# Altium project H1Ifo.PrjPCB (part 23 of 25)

## Sheet IfoSqz4A.SchDoc: D1800185
size C; Engineer: Daniel Sigg; DocumentNumber: 8; Revision: 4; SheetNumber: 8; SheetTotal: 10
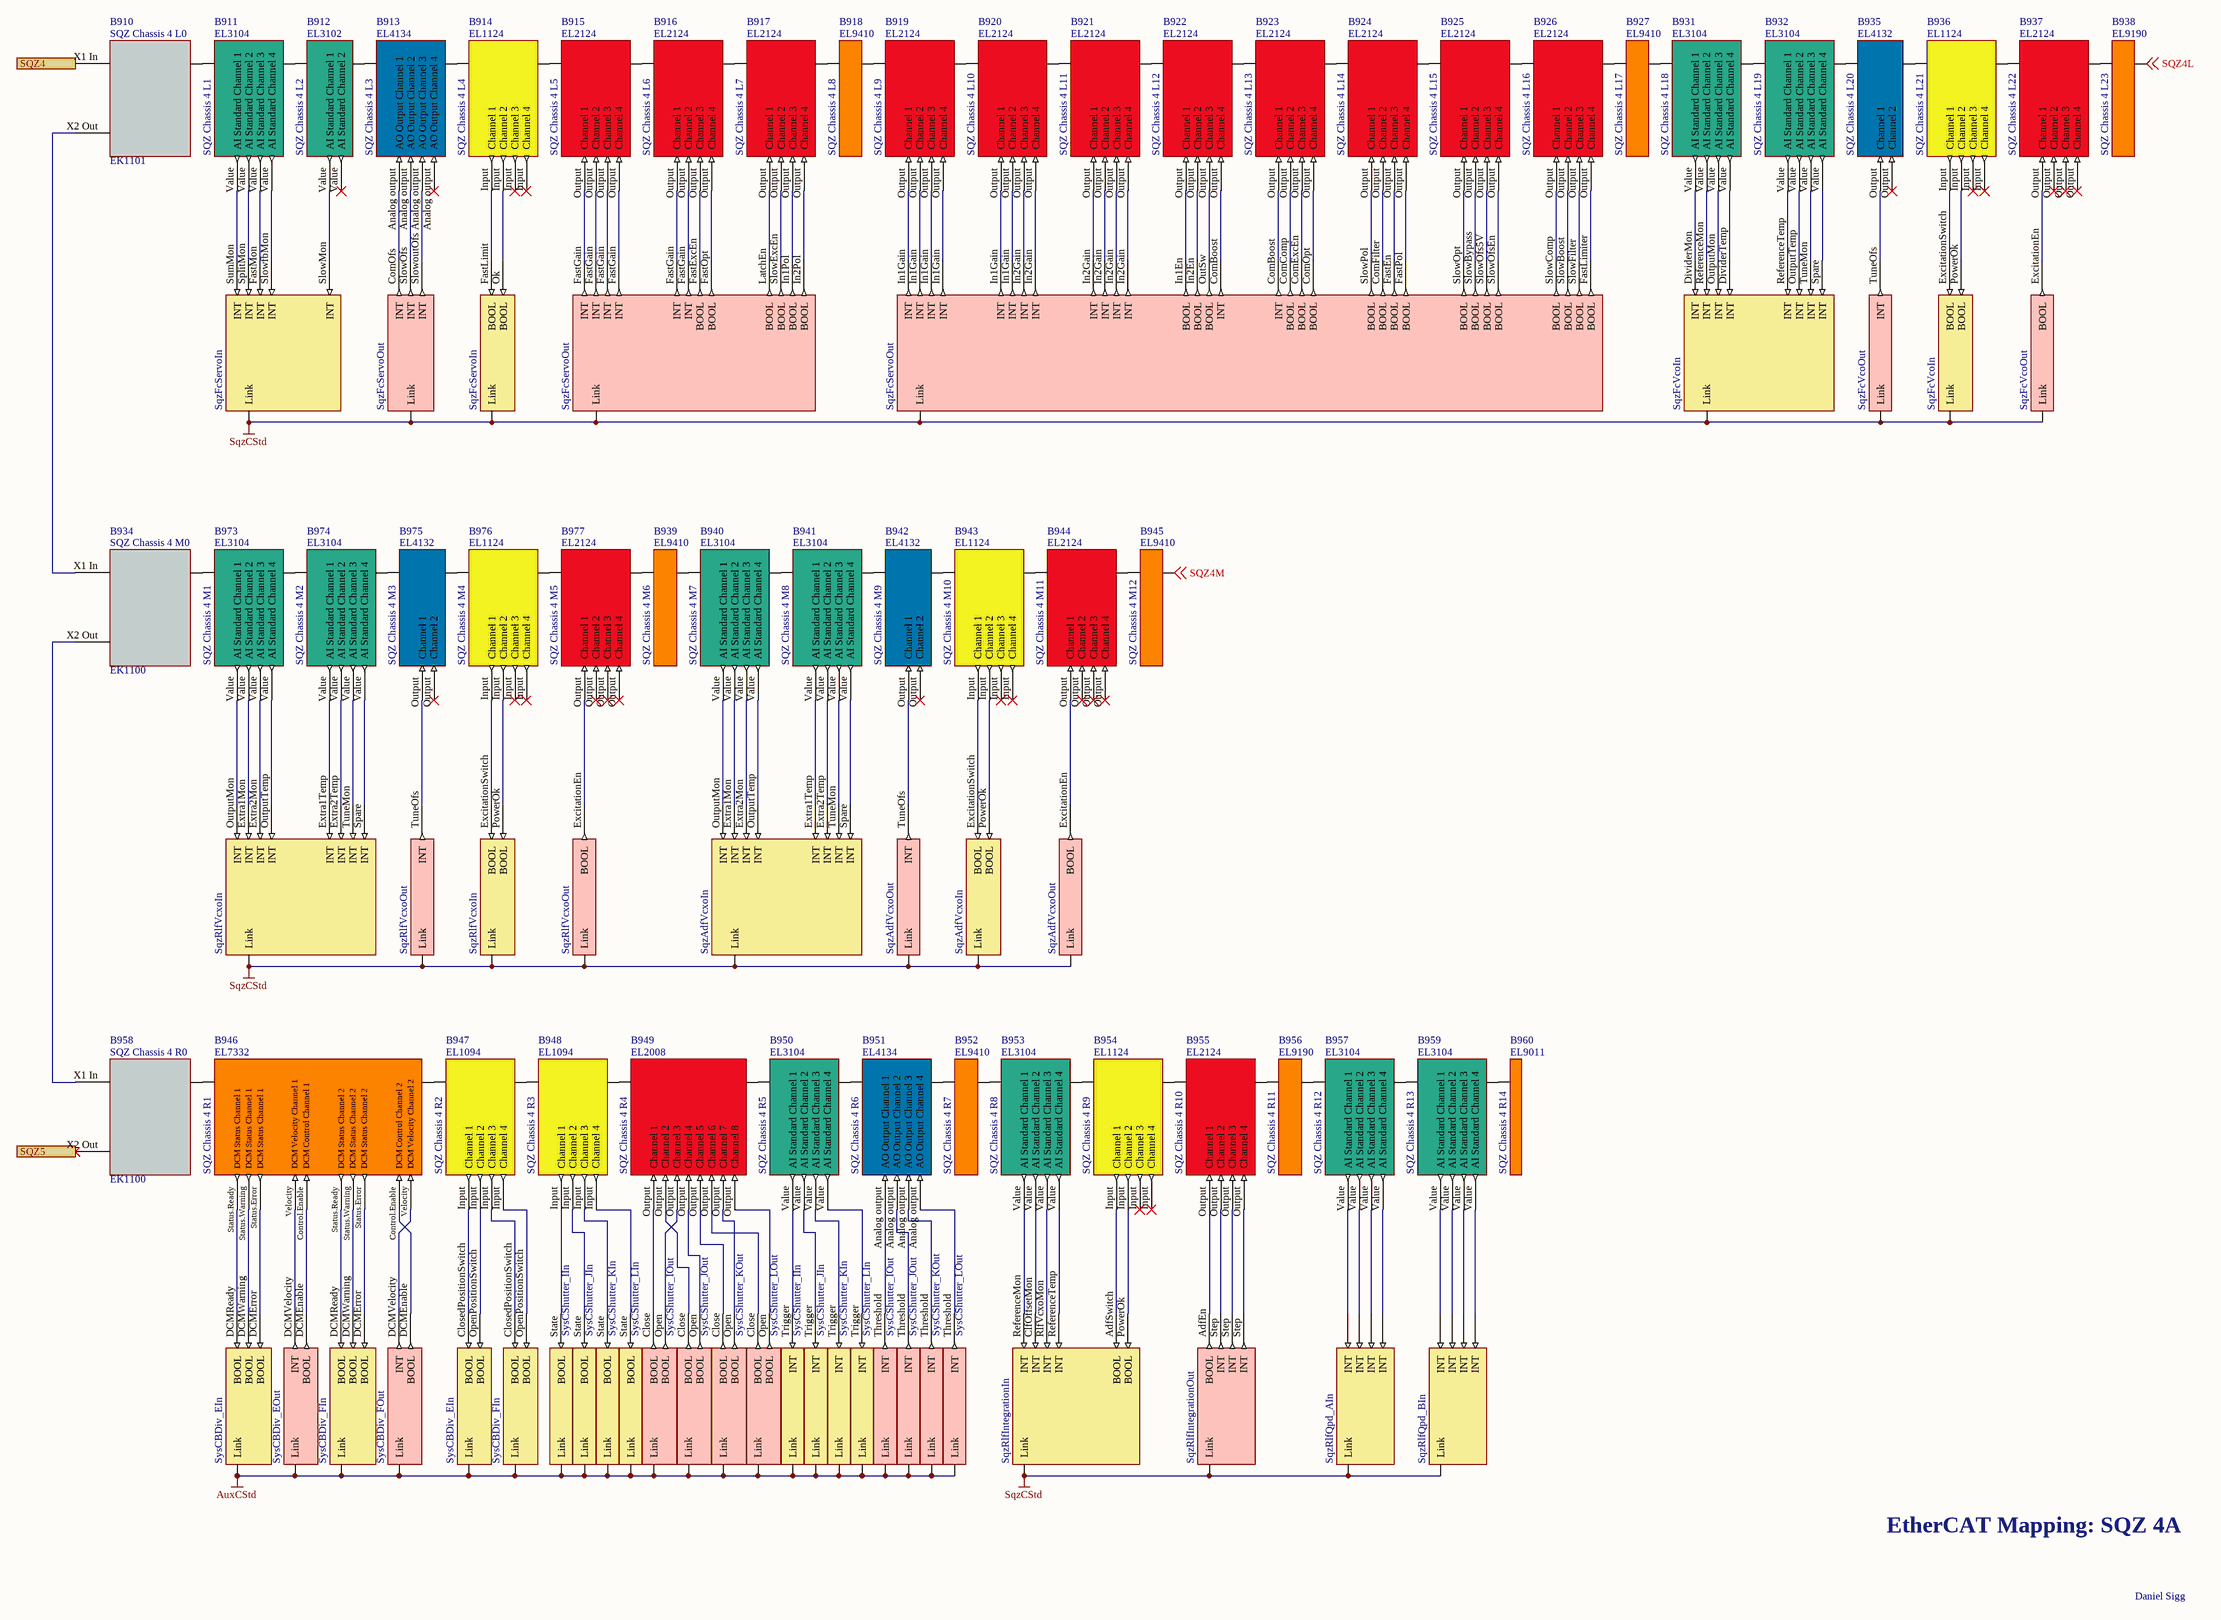
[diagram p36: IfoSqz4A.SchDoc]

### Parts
B910  SQZ Chassis 4 L0  Part Number: EK1101
B911  SQZ Chassis 4 L1  Part Number: EL3104  (mechanical)
B912  SQZ Chassis 4 L2  Part Number: EL3102  (mechanical)
B913  SQZ Chassis 4 L3  Part Number: EL4134  (mechanical)
B914  SQZ Chassis 4 L4  Part Number: EL1124  (mechanical)
B915  SQZ Chassis 4 L5  Part Number: EL2124  (mechanical)
B916  SQZ Chassis 4 L6  Part Number: EL2124  (mechanical)
B917  SQZ Chassis 4 L7  Part Number: EL2124  (mechanical)
B918  SQZ Chassis 4 L8  Part Number: EL9410  (mechanical)
B919  SQZ Chassis 4 L9  Part Number: EL2124  (mechanical)
B920  SQZ Chassis 4 L10  Part Number: EL2124  (mechanical)
B921  SQZ Chassis 4 L11  Part Number: EL2124  (mechanical)
B922  SQZ Chassis 4 L12  Part Number: EL2124  (mechanical)
B923  SQZ Chassis 4 L13  Part Number: EL2124  (mechanical)
B924  SQZ Chassis 4 L14  Part Number: EL2124  (mechanical)
B925  SQZ Chassis 4 L15  Part Number: EL2124  (mechanical)
B926  SQZ Chassis 4 L16  Part Number: EL2124  (mechanical)
B927  SQZ Chassis 4 L17  Part Number: EL9410  (mechanical)
B931  SQZ Chassis 4 L18  Part Number: EL3104  (mechanical)
B932  SQZ Chassis 4 L19  Part Number: EL3104  (mechanical)
B934  SQZ Chassis 4 M0  Part Number: EK1100
B935  SQZ Chassis 4 L20  Part Number: EL4132  (mechanical)
B936  SQZ Chassis 4 L21  Part Number: EL1124  (mechanical)
B937  SQZ Chassis 4 L22  Part Number: EL2124  (mechanical)
B938  SQZ Chassis 4 L23  Part Number: EL9190  (mechanical)
B939  SQZ Chassis 4 M6  Part Number: EL9410  (mechanical)
B940  SQZ Chassis 4 M7  Part Number: EL3104  (mechanical)
B941  SQZ Chassis 4 M8  Part Number: EL3104  (mechanical)
B942  SQZ Chassis 4 M9  Part Number: EL4132  (mechanical)
B943  SQZ Chassis 4 M10  Part Number: EL1124  (mechanical)
B944  SQZ Chassis 4 M11  Part Number: EL2124  (mechanical)
B945  SQZ Chassis 4 M12  Part Number: EL9410  (mechanical)
B946  SQZ Chassis 4 R1  Part Number: EL7332  (mechanical)
B947  SQZ Chassis 4 R2  Part Number: EL1094  (mechanical)
B948  SQZ Chassis 4 R3  Part Number: EL1094  (mechanical)
B949  SQZ Chassis 4 R4  Part Number: EL2008  (mechanical)
B950  SQZ Chassis 4 R5  Part Number: EL3104  (mechanical)
B951  SQZ Chassis 4 R6  Part Number: EL4134  (mechanical)
B952  SQZ Chassis 4 R7  Part Number: EL9410  (mechanical)
B953  SQZ Chassis 4 R8  Part Number: EL3104  (mechanical)
B954  SQZ Chassis 4 R9  Part Number: EL1124  (mechanical)
B955  SQZ Chassis 4 R10  Part Number: EL2124  (mechanical)
B956  SQZ Chassis 4 R11  Part Number: EL9190  (mechanical)
B957  SQZ Chassis 4 R12  Part Number: EL3104  (mechanical)
B958  SQZ Chassis 4 R0  Part Number: EK1100
B959  SQZ Chassis 4 R13  Part Number: EL3104  (mechanical)
B960  SQZ Chassis 4 R14  Part Number: EL9011  (mechanical)
B973  SQZ Chassis 4 M1  Part Number: EL3104  (mechanical)
B974  SQZ Chassis 4 M2  Part Number: EL3104  (mechanical)
B975  SQZ Chassis 4 M3  Part Number: EL4132  (mechanical)
B976  SQZ Chassis 4 M4  Part Number: EL1124  (mechanical)
B977  SQZ Chassis 4 M5  Part Number: EL2124  (mechanical)
V744  SqzFcServoIn  (parts A,B of 2)  (no BOM)
V745  SqzFcServoOut  (parts A,B,C of 3)  (no BOM)
V747  SqzFcVcoOut  (parts A,B of 2)  (no BOM)
V748  SysCBDiv_EOut  (no BOM)
V749  SysCBDiv_FOut  (no BOM)
V774  SqzRlfVcxoIn  (parts A,B of 2)  (no BOM)
V775  SqzRlfVcxoOut  (parts A,B of 2)  (no BOM)
V776  SqzAdfVcxoIn  (parts A,B of 2)  (no BOM)
V777  SqzAdfVcxoOut  (parts A,B of 2)  (no BOM)
V778  SysCBDiv_EIn  (parts A,B of 2)  (no BOM)
V779  SysCBDiv_FIn  (parts A,B of 2)  (no BOM)
V780  SysCShutter_IIn  (parts A,B of 2)  (no BOM)
V781  SysCShutter_JIn  (parts A,B of 2)  (no BOM)
V782  SysCShutter_KIn  (parts A,B of 2)  (no BOM)
V783  SysCShutter_LIn  (parts A,B of 2)  (no BOM)
V784  SysCShutter_IOut  (parts A,B of 2)  (no BOM)
V785  SysCShutter_JOut  (parts A,B of 2)  (no BOM)
V786  SysCShutter_KOut  (parts A,B of 2)  (no BOM)
V787  SysCShutter_LOut  (parts A,B of 2)  (no BOM)
V796  SqzFcVcoIn  (parts A,B of 2)  (no BOM)
V797  SqzRlfIntegrationIn  (no BOM)
V798  SqzRlfIntegrationOut  (no BOM)
V799  SqzRlfQpd_AIn  (no BOM)
V800  SqzRlfQpd_BIn  (no BOM)

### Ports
SQZ4, SQZ5

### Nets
AuxCStd: V748.0(Link) V749.0(Link) V778.0(Link) V778.1(Link) V779.0(Link) V779.1(Link) V780.0(Link) V780.1(Link) V781.0(Link) V781.1(Link) V782.0(Link) V782.1(Link) V783.0(Link) V783.1(Link) V784.0(Link) V784.1(Link) V785.0(Link) V785.1(Link) V786.0(Link) V786.1(Link) V787.0(Link) V787.1(Link)
SqzCStd: V744.0(Link) V744.1(Link) V745.0(Link) V745.1(Link) V745.2(Link) V747.0(Link) V747.1(Link) V774.0(Link) V774.1(Link) V775.0(Link) V775.1(Link) V776.0(Link) V776.1(Link) V777.0(Link) V777.1(Link) V796.0(Link) V796.1(Link) V797.0(Link) V798.1(Link) V799.1(Link) V800.1(Link)
SQZ4L: B938.Ebus(B) ; off-sheet SQZ4L
SQZ4M: B945.Ebus(B) ; off-sheet SQZ4M
NetB746#2_X1 In: B958.X2_Out(C) ; port SQZ5
NetB886_X2 Out: B910.X1_In(A) ; port SQZ4
NetB910_Ebus: B910.Ebus(B) B911.Ebus(A)
NetB910_X2 Out: B910.X2_Out(C) B934.X1_In(A)
NetB911_Ebus: B911.Ebus(B) B912.Ebus(A)
NetB911_Value: B911.Value(AI_Standard_Channel_1) V744.SumMon(INT)
NetB911_Value: B911.Value(AI_Standard_Channel_2) V744.SplitMon(INT)  [a separate net that carries the same name]
NetB911_Value: B911.Value(AI_Standard_Channel_3) V744.FastMon(INT)  [a separate net that carries the same name]
NetB911_Value: B911.Value(AI_Standard_Channel_4) V744.SlowfbMon(INT)  [a separate net that carries the same name]
NetB912_Ebus: B912.Ebus(B) B913.Ebus(A)
NetB912_Value: B912.Value(AI_Standard_Channel_1) V744.SlowMon(INT)
NetB913_Analog output: B913.Analog_output(AO_Output_Channel_1) V745.ComOfs(INT)
NetB913_Analog output: B913.Analog_output(AO_Output_Channel_2) V745.SlowOfs(INT)  [a separate net that carries the same name]
NetB913_Analog output: B913.Analog_output(AO_Output_Channel_3) V745.SlowoutOfs(INT)  [a separate net that carries the same name]
NetB913_Ebus: B913.Ebus(B) B914.Ebus(A)
NetB914_Ebus: B914.Ebus(B) B915.Ebus(A)
NetB914_Input: B914.Input(Channel_1) V744.FastLimit(BOOL)
NetB914_Input: B914.Input(Channel_2) V744.Ok(BOOL)  [a separate net that carries the same name]
NetB915_Ebus: B915.Ebus(B) B916.Ebus(A)
NetB915_Output: B915.Output(Channel_1) V745.FastGain(INT)
NetB915_Output: B915.Output(Channel_2) V745.FastGain(INT)  [a separate net that carries the same name]
NetB915_Output: B915.Output(Channel_3) V745.FastGain(INT)  [a separate net that carries the same name]
NetB915_Output: B915.Output(Channel_4) V745.FastGain(INT)  [a separate net that carries the same name]
NetB916_Ebus: B916.Ebus(B) B917.Ebus(A)
NetB916_Output: B916.Output(Channel_1) V745.FastGain(INT)
NetB916_Output: B916.Output(Channel_2) V745.FastGain(INT)  [a separate net that carries the same name]
NetB916_Output: B916.Output(Channel_3) V745.FastExcEn(BOOL)  [a separate net that carries the same name]
NetB916_Output: B916.Output(Channel_4) V745.FastOpt(BOOL)  [a separate net that carries the same name]
NetB917_Ebus: B917.Ebus(B) B918.Ebus(A)
NetB917_Output: B917.Output(Channel_1) V745.LatchEn(BOOL)
NetB917_Output: B917.Output(Channel_2) V745.SlowExcEn(BOOL)  [a separate net that carries the same name]
NetB917_Output: B917.Output(Channel_3) V745.In1Pol(BOOL)  [a separate net that carries the same name]
NetB917_Output: B917.Output(Channel_4) V745.In2Pol(BOOL)  [a separate net that carries the same name]
NetB918_Ebus: B918.Ebus(B) B919.Ebus(A)
NetB919_Ebus: B919.Ebus(B) B920.Ebus(A)
NetB919_Output: B919.Output(Channel_1) V745.In1Gain(INT)
NetB919_Output: B919.Output(Channel_2) V745.In1Gain(INT)  [a separate net that carries the same name]
NetB919_Output: B919.Output(Channel_3) V745.In1Gain(INT)  [a separate net that carries the same name]
NetB919_Output: B919.Output(Channel_4) V745.In1Gain(INT)  [a separate net that carries the same name]
NetB920_Ebus: B920.Ebus(B) B921.Ebus(A)
NetB920_Output: B920.Output(Channel_1) V745.In1Gain(INT)
NetB920_Output: B920.Output(Channel_2) V745.In1Gain(INT)  [a separate net that carries the same name]
NetB920_Output: B920.Output(Channel_3) V745.In2Gain(INT)  [a separate net that carries the same name]
NetB920_Output: B920.Output(Channel_4) V745.In2Gain(INT)  [a separate net that carries the same name]
NetB921_Ebus: B921.Ebus(B) B922.Ebus(A)
NetB921_Output: B921.Output(Channel_1) V745.In2Gain(INT)
NetB921_Output: B921.Output(Channel_2) V745.In2Gain(INT)  [a separate net that carries the same name]
NetB921_Output: B921.Output(Channel_3) V745.In2Gain(INT)  [a separate net that carries the same name]
NetB921_Output: B921.Output(Channel_4) V745.In2Gain(INT)  [a separate net that carries the same name]
NetB922_Ebus: B922.Ebus(B) B923.Ebus(A)
NetB922_Output: B922.Output(Channel_1) V745.In1En(BOOL)
NetB922_Output: B922.Output(Channel_2) V745.In2En(BOOL)  [a separate net that carries the same name]
NetB922_Output: B922.Output(Channel_3) V745.OutSw(BOOL)  [a separate net that carries the same name]
NetB922_Output: B922.Output(Channel_4) V745.ComBoost(INT)  [a separate net that carries the same name]
NetB923_Ebus: B923.Ebus(B) B924.Ebus(A)
NetB923_Output: B923.Output(Channel_1) V745.ComBoost(INT)
NetB923_Output: B923.Output(Channel_2) V745.ComComp(BOOL)  [a separate net that carries the same name]
NetB923_Output: B923.Output(Channel_3) V745.ComExcEn(BOOL)  [a separate net that carries the same name]
NetB923_Output: B923.Output(Channel_4) V745.ComOpt(BOOL)  [a separate net that carries the same name]
NetB924_Ebus: B924.Ebus(B) B925.Ebus(A)
NetB924_Output: B924.Output(Channel_1) V745.SlowPol(BOOL)
NetB924_Output: B924.Output(Channel_2) V745.ComFilter(BOOL)  [a separate net that carries the same name]
NetB924_Output: B924.Output(Channel_3) V745.FastEn(BOOL)  [a separate net that carries the same name]
NetB924_Output: B924.Output(Channel_4) V745.FastPol(BOOL)  [a separate net that carries the same name]
NetB925_Ebus: B925.Ebus(B) B926.Ebus(A)
NetB925_Output: B925.Output(Channel_1) V745.SlowOpt(BOOL)
NetB925_Output: B925.Output(Channel_2) V745.SlowBypass(BOOL)  [a separate net that carries the same name]
NetB925_Output: B925.Output(Channel_3) V745.SlowOfs5V(BOOL)  [a separate net that carries the same name]
NetB925_Output: B925.Output(Channel_4) V745.SlowOfsEn(BOOL)  [a separate net that carries the same name]
NetB926_Ebus: B926.Ebus(B) B927.Ebus(A)
NetB926_Output: B926.Output(Channel_1) V745.SlowComp(BOOL)
NetB926_Output: B926.Output(Channel_2) V745.SlowBoost(BOOL)  [a separate net that carries the same name]
NetB926_Output: B926.Output(Channel_3) V745.SlowFilter(BOOL)  [a separate net that carries the same name]
NetB926_Output: B926.Output(Channel_4) V745.FastLimiter(BOOL)  [a separate net that carries the same name]
NetB927_Ebus: B927.Ebus(B) B931.Ebus(A)
NetB931_Ebus: B931.Ebus(B) B932.Ebus(A)
NetB931_Value: B931.Value(AI_Standard_Channel_1) V796.DividerMon(INT)
NetB931_Value: B931.Value(AI_Standard_Channel_2) V796.ReferenceMon(INT)  [a separate net that carries the same name]
NetB931_Value: B931.Value(AI_Standard_Channel_3) V796.OutputMon(INT)  [a separate net that carries the same name]
NetB931_Value: B931.Value(AI_Standard_Channel_4) V796.DividerTemp(INT)  [a separate net that carries the same name]
NetB932_Ebus: B932.Ebus(B) B935.Ebus(A)
NetB932_Value: B932.Value(AI_Standard_Channel_1) V796.ReferenceTemp(INT)
NetB932_Value: B932.Value(AI_Standard_Channel_2) V796.OutputTemp(INT)  [a separate net that carries the same name]
NetB932_Value: B932.Value(AI_Standard_Channel_3) V796.TuneMon(INT)  [a separate net that carries the same name]
NetB932_Value: B932.Value(AI_Standard_Channel_4) V796.Spare(INT)  [a separate net that carries the same name]
NetB934_Ebus: B934.Ebus(B) B973.Ebus(A)
NetB934_X2 Out: B934.X2_Out(C) B958.X1_In(A)
NetB935_Ebus: B935.Ebus(B) B936.Ebus(A)
NetB935_Output: B935.Output(Channel_1) V747.TuneOfs(INT)
NetB936_Ebus: B936.Ebus(B) B937.Ebus(A)
NetB936_Input: B936.Input(Channel_1) V796.ExcitationSwitch(BOOL)
NetB936_Input: B936.Input(Channel_2) V796.PowerOk(BOOL)  [a separate net that carries the same name]
NetB937_Ebus: B937.Ebus(B) B938.Ebus(A)
NetB937_Output: B937.Output(Channel_1) V747.ExcitationEn(BOOL)
NetB939_Ebus: B939.Ebus(A) B977.Ebus(B)
NetB939_Ebus: B939.Ebus(B) B940.Ebus(A)  [a separate net that carries the same name]
NetB940_Ebus: B940.Ebus(B) B941.Ebus(A)
NetB940_Value: B940.Value(AI_Standard_Channel_1) V776.OutputMon(INT)
NetB940_Value: B940.Value(AI_Standard_Channel_2) V776.Extra1Mon(INT)  [a separate net that carries the same name]
NetB940_Value: B940.Value(AI_Standard_Channel_3) V776.Extra2Mon(INT)  [a separate net that carries the same name]
NetB940_Value: B940.Value(AI_Standard_Channel_4) V776.OutputTemp(INT)  [a separate net that carries the same name]
NetB941_Ebus: B941.Ebus(B) B942.Ebus(A)
NetB941_Value: B941.Value(AI_Standard_Channel_1) V776.Extra1Temp(INT)
NetB941_Value: B941.Value(AI_Standard_Channel_2) V776.Extra2Temp(INT)  [a separate net that carries the same name]
NetB941_Value: B941.Value(AI_Standard_Channel_3) V776.TuneMon(INT)  [a separate net that carries the same name]
NetB941_Value: B941.Value(AI_Standard_Channel_4) V776.Spare(INT)  [a separate net that carries the same name]
NetB942_Ebus: B942.Ebus(B) B943.Ebus(A)
NetB942_Output: B942.Output(Channel_1) V777.TuneOfs(INT)
NetB943_Ebus: B943.Ebus(B) B944.Ebus(A)
NetB943_Input: B943.Input(Channel_1) V776.ExcitationSwitch(BOOL)
NetB943_Input: B943.Input(Channel_2) V776.PowerOk(BOOL)  [a separate net that carries the same name]
NetB944_Ebus: B944.Ebus(B) B945.Ebus(A)
NetB944_Output: B944.Output(Channel_1) V777.ExcitationEn(BOOL)
NetB946_Control.Enable: B946.Control.Enable(DCM_Control_Channel_1) V748.DCMEnable(BOOL)
NetB946_Control.Enable: B946.Control.Enable(DCM_Control_Channel_2) V749.DCMEnable(BOOL)  [a separate net that carries the same name]
NetB946_Ebus: B946.Ebus(A) B958.Ebus(B)
NetB946_Ebus: B946.Ebus(B) B947.Ebus(A)  [a separate net that carries the same name]
NetB946_Status.Error: B946.Status.Error(DCM_Status_Channel_1) V778.DCMError(BOOL)
NetB946_Status.Error: B946.Status.Error(DCM_Status_Channel_2) V779.DCMError(BOOL)  [a separate net that carries the same name]
NetB946_Status.Ready: B946.Status.Ready(DCM_Status_Channel_1) V778.DCMReady(BOOL)
NetB946_Status.Ready: B946.Status.Ready(DCM_Status_Channel_2) V779.DCMReady(BOOL)  [a separate net that carries the same name]
NetB946_Status.Warning: B946.Status.Warning(DCM_Status_Channel_1) V778.DCMWarning(BOOL)
NetB946_Status.Warning: B946.Status.Warning(DCM_Status_Channel_2) V779.DCMWarning(BOOL)  [a separate net that carries the same name]
NetB946_Velocity: B946.Velocity(DCM_Velocity_Channel_1) V748.DCMVelocity(INT)
NetB946_Velocity: B946.Velocity(DCM_Velocity_Channel_2) V749.DCMVelocity(INT)  [a separate net that carries the same name]
NetB947_Ebus: B947.Ebus(B) B948.Ebus(A)
NetB947_Input: B947.Input(Channel_1) V778.ClosedPositionSwitch(BOOL)
NetB947_Input: B947.Input(Channel_2) V778.OpenPositionSwitch(BOOL)  [a separate net that carries the same name]
NetB947_Input: B947.Input(Channel_3) V779.ClosedPositionSwitch(BOOL)  [a separate net that carries the same name]
NetB947_Input: B947.Input(Channel_4) V779.OpenPositionSwitch(BOOL)  [a separate net that carries the same name]
NetB948_Ebus: B948.Ebus(B) B949.Ebus(A)
NetB948_Input: B948.Input(Channel_1) V780.State(BOOL)
NetB948_Input: B948.Input(Channel_2) V781.State(BOOL)  [a separate net that carries the same name]
NetB948_Input: B948.Input(Channel_3) V782.State(BOOL)  [a separate net that carries the same name]
NetB948_Input: B948.Input(Channel_4) V783.State(BOOL)  [a separate net that carries the same name]
NetB949_Ebus: B949.Ebus(B) B950.Ebus(A)
NetB949_Output: B949.Output(Channel_1) V784.Close(BOOL)
NetB949_Output: B949.Output(Channel_2) V785.Close(BOOL)  [a separate net that carries the same name]
NetB949_Output: B949.Output(Channel_3) V784.Open(BOOL)  [a separate net that carries the same name]
NetB949_Output: B949.Output(Channel_4) V785.Open(BOOL)  [a separate net that carries the same name]
NetB949_Output: B949.Output(Channel_5) V786.Close(BOOL)  [a separate net that carries the same name]
NetB949_Output: B949.Output(Channel_6) V787.Close(BOOL)  [a separate net that carries the same name]
NetB949_Output: B949.Output(Channel_7) V786.Open(BOOL)  [a separate net that carries the same name]
NetB949_Output: B949.Output(Channel_8) V787.Open(BOOL)  [a separate net that carries the same name]
NetB950_Ebus: B950.Ebus(B) B951.Ebus(A)
NetB950_Value: B950.Value(AI_Standard_Channel_1) V780.Trigger(INT)
NetB950_Value: B950.Value(AI_Standard_Channel_2) V781.Trigger(INT)  [a separate net that carries the same name]
NetB950_Value: B950.Value(AI_Standard_Channel_3) V782.Trigger(INT)  [a separate net that carries the same name]
NetB950_Value: B950.Value(AI_Standard_Channel_4) V783.Trigger(INT)  [a separate net that carries the same name]
NetB951_Analog output: B951.Analog_output(AO_Output_Channel_1) V784.Threshold(INT)
NetB951_Analog output: B951.Analog_output(AO_Output_Channel_2) V785.Threshold(INT)  [a separate net that carries the same name]
NetB951_Analog output: B951.Analog_output(AO_Output_Channel_3) V786.Threshold(INT)  [a separate net that carries the same name]
NetB951_Analog output: B951.Analog_output(AO_Output_Channel_4) V787.Threshold(INT)  [a separate net that carries the same name]
NetB951_Ebus: B951.Ebus(B) B952.Ebus(A)
NetB952_Ebus: B952.Ebus(B) B953.Ebus(A)
NetB953_Ebus: B953.Ebus(B) B954.Ebus(A)
NetB953_Value: B953.Value(AI_Standard_Channel_1) V797.ReferenceMon(INT)
NetB953_Value: B953.Value(AI_Standard_Channel_2) V797.ClfOffsetMon(INT)  [a separate net that carries the same name]
NetB953_Value: B953.Value(AI_Standard_Channel_3) V797.RlfVcxoMon(INT)  [a separate net that carries the same name]
NetB953_Value: B953.Value(AI_Standard_Channel_4) V797.ReferenceTemp(INT)  [a separate net that carries the same name]
NetB954_Ebus: B954.Ebus(B) B955.Ebus(A)
NetB954_Input: B954.Input(Channel_1) V797.AdfSwitch(BOOL)
NetB954_Input: B954.Input(Channel_2) V797.PowerOk(BOOL)  [a separate net that carries the same name]
NetB955_Ebus: B955.Ebus(B) B956.Ebus(A)
NetB955_Output: B955.Output(Channel_1) V798.AdfEn(BOOL)
NetB955_Output: B955.Output(Channel_2) V798.Step(INT)  [a separate net that carries the same name]
NetB955_Output: B955.Output(Channel_3) V798.Step(INT)  [a separate net that carries the same name]
NetB955_Output: B955.Output(Channel_4) V798.Step(INT)  [a separate net that carries the same name]
NetB956_Ebus: B956.Ebus(B) B957.Ebus(A)
NetB957_Ebus: B957.Ebus(B) B959.Ebus(A)
NetB957_Value: B957.Value(AI_Standard_Channel_1) V799.Seg4Dc(INT)
NetB957_Value: B957.Value(AI_Standard_Channel_2) V799.Seg3Dc(INT)  [a separate net that carries the same name]
NetB957_Value: B957.Value(AI_Standard_Channel_3) V799.Seg1Dc(INT)  [a separate net that carries the same name]
NetB957_Value: B957.Value(AI_Standard_Channel_4) V799.Seg2Dc(INT)  [a separate net that carries the same name]
NetB959_Ebus: B959.Ebus(B) B960.Ebus(A)
NetB959_Value: B959.Value(AI_Standard_Channel_1) V800.Seg4Dc(INT)
NetB959_Value: B959.Value(AI_Standard_Channel_2) V800.Seg3Dc(INT)  [a separate net that carries the same name]
NetB959_Value: B959.Value(AI_Standard_Channel_3) V800.Seg1Dc(INT)  [a separate net that carries the same name]
NetB959_Value: B959.Value(AI_Standard_Channel_4) V800.Seg2Dc(INT)  [a separate net that carries the same name]
NetB973_Ebus: B973.Ebus(B) B974.Ebus(A)
NetB973_Value: B973.Value(AI_Standard_Channel_1) V774.OutputMon(INT)
NetB973_Value: B973.Value(AI_Standard_Channel_2) V774.Extra1Mon(INT)  [a separate net that carries the same name]
NetB973_Value: B973.Value(AI_Standard_Channel_3) V774.Extra2Mon(INT)  [a separate net that carries the same name]
NetB973_Value: B973.Value(AI_Standard_Channel_4) V774.OutputTemp(INT)  [a separate net that carries the same name]
NetB974_Ebus: B974.Ebus(B) B975.Ebus(A)
NetB974_Value: B974.Value(AI_Standard_Channel_1) V774.Extra1Temp(INT)
NetB974_Value: B974.Value(AI_Standard_Channel_2) V774.Extra2Temp(INT)  [a separate net that carries the same name]
NetB974_Value: B974.Value(AI_Standard_Channel_3) V774.TuneMon(INT)  [a separate net that carries the same name]
NetB974_Value: B974.Value(AI_Standard_Channel_4) V774.Spare(INT)  [a separate net that carries the same name]
NetB975_Ebus: B975.Ebus(B) B976.Ebus(A)
NetB975_Output: B975.Output(Channel_1) V775.TuneOfs(INT)
NetB976_Ebus: B976.Ebus(B) B977.Ebus(A)
NetB976_Input: B976.Input(Channel_1) V774.ExcitationSwitch(BOOL)
NetB976_Input: B976.Input(Channel_2) V774.PowerOk(BOOL)  [a separate net that carries the same name]
NetB977_Output: B977.Output(Channel_1) V775.ExcitationEn(BOOL)

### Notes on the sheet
- EtherCAT Mapping: SQZ 4A
- Daniel Sigg

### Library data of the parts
B910 = CouplerEK1101: EtherCAT Coupler; Rail: Left; BoxNextB: JTLFXJNX; BoxNextC: CKSSHHCU; BoxPrev: BKUDMEPV; PortPrevFull: 1168/C; PortPrevShort: C 'X2 Out'; Fullname: TIID^Vertex Squeezer (EtherCAT)^SQZ Chassis 4 L0 (EK1101); BoxPorts: Junction; BoxAddr: 1188; Disabled: False
B911 = TerminalEL3104: EtherCAT Terminal EL3104 4-chn Analog Input; Rail: Left; BoxNextB: RXMGGCEI; BoxPrev: BCNOLNHC; PortPrevFull: 1188/B; PortPrevShort: B; Fullname: TIID^Vertex Squeezer (EtherCAT)^SQZ Chassis 4 L0 (EK1101)^SQZ Chassis 4 L1 (EL3104); BoxAddr: 1189; Disabled: False
B912 = TerminalEL3102: EtherCAT Terminal EL3102 2-chn Analog Input; Rail: Left; BoxNextB: QRUXMSAU; BoxPrev: JTLFXJNX; PortPrevFull: 1189/B; PortPrevShort: B; Fullname: TIID^Vertex Squeezer (EtherCAT)^SQZ Chassis 4 L0 (EK1101)^SQZ Chassis 4 L2 (EL3102); BoxAddr: 1190; Disabled: False
B913 = TerminalEL4134: EtherCAT Terminal EL4134 4-chn Analog Ouput; Rail: Left; BoxNextB: KEVJOHYG; BoxPrev: RXMGGCEI; PortPrevFull: 1190/B; PortPrevShort: B; Fullname: TIID^Vertex Squeezer (EtherCAT)^SQZ Chassis 4 L0 (EK1101)^SQZ Chassis 4 L3 (EL4134); BoxAddr: 1191; Disabled: False
B914 = TerminalEL1124: EtherCAT Terminal EL1124 4-chn Digital Input; Rail: Left; BoxNextB: XQQAHJLW; BoxPrev: QRUXMSAU; PortPrevFull: 1191/B; PortPrevShort: B; Fullname: TIID^Vertex Squeezer (EtherCAT)^SQZ Chassis 4 L0 (EK1101)^SQZ Chassis 4 L4 (EL1124); BoxAddr: 1192; Disabled: False
B915 = TerminalEL2124: EtherCAT Terminal EL2124 4-chn Digital Ouput; Rail: Left; BoxNextB: SEPSBOXG; BoxPrev: KEVJOHYG; PortPrevFull: 1192/B; PortPrevShort: B; Fullname: TIID^Vertex Squeezer (EtherCAT)^SQZ Chassis 4 L0 (EK1101)^SQZ Chassis 4 L5 (EL2124); BoxAddr: 1193; Disabled: False
B916 = TerminalEL2124: EtherCAT Terminal EL2124 4-chn Digital Ouput; Rail: Left; BoxNextB: EEVYYAYS; BoxPrev: XQQAHJLW; PortPrevFull: 1193/B; PortPrevShort: B; Fullname: TIID^Vertex Squeezer (EtherCAT)^SQZ Chassis 4 L0 (EK1101)^SQZ Chassis 4 L6 (EL2124); BoxAddr: 1194; Disabled: False
B917 = TerminalEL2124: EtherCAT Terminal EL2124 4-chn Digital Ouput; Rail: Left; BoxNextB: TYLYDKYN; BoxPrev: SEPSBOXG; PortPrevFull: 1194/B; PortPrevShort: B; Fullname: TIID^Vertex Squeezer (EtherCAT)^SQZ Chassis 4 L0 (EK1101)^SQZ Chassis 4 L7 (EL2124); BoxAddr: 1195; Disabled: False
B918 = TerminalEL9410: EtherCAT Terminal EL9410 Power; Rail: Left; BoxNextB: WFLVLTIK; BoxPrev: EEVYYAYS; PortPrevFull: 1195/B; PortPrevShort: B; Fullname: TIID^Vertex Squeezer (EtherCAT)^SQZ Chassis 4 L0 (EK1101)^SQZ Chassis 4 L8 (EL9410); BoxAddr: 1196; Disabled: False
B919 = TerminalEL2124: EtherCAT Terminal EL2124 4-chn Digital Ouput; Rail: Left; BoxNextB: FUNGBFOC; BoxPrev: TYLYDKYN; PortPrevFull: 1196/B; PortPrevShort: B; Fullname: TIID^Vertex Squeezer (EtherCAT)^SQZ Chassis 4 L0 (EK1101)^SQZ Chassis 4 L9 (EL2124); BoxAddr: 1197; Disabled: False
B920 = TerminalEL2124: EtherCAT Terminal EL2124 4-chn Digital Ouput; Rail: Left; BoxNextB: YQBEXIPJ; BoxPrev: WFLVLTIK; PortPrevFull: 1197/B; PortPrevShort: B; Fullname: TIID^Vertex Squeezer (EtherCAT)^SQZ Chassis 4 L0 (EK1101)^SQZ Chassis 4 L10 (EL2124); BoxAddr: 1198; Disabled: False
B921 = TerminalEL2124: EtherCAT Terminal EL2124 4-chn Digital Ouput; Rail: Left; BoxNextB: IIFTQPBX; BoxPrev: FUNGBFOC; PortPrevFull: 1198/B; PortPrevShort: B; Fullname: TIID^Vertex Squeezer (EtherCAT)^SQZ Chassis 4 L0 (EK1101)^SQZ Chassis 4 L11 (EL2124); BoxAddr: 1199; Disabled: False
B922 = TerminalEL2124: EtherCAT Terminal EL2124 4-chn Digital Ouput; Rail: Left; BoxNextB: HCBALMVB; BoxPrev: YQBEXIPJ; PortPrevFull: 1199/B; PortPrevShort: B; Fullname: TIID^Vertex Squeezer (EtherCAT)^SQZ Chassis 4 L0 (EK1101)^SQZ Chassis 4 L12 (EL2124); BoxAddr: 1200; Disabled: False
B923 = TerminalEL2124: EtherCAT Terminal EL2124 4-chn Digital Ouput; Rail: Left; BoxNextB: IADPCTYX; BoxPrev: IIFTQPBX; PortPrevFull: 1200/B; PortPrevShort: B; Fullname: TIID^Vertex Squeezer (EtherCAT)^SQZ Chassis 4 L0 (EK1101)^SQZ Chassis 4 L13 (EL2124); BoxAddr: 1201; Disabled: False
B924 = TerminalEL2124: EtherCAT Terminal EL2124 4-chn Digital Ouput; Rail: Left; BoxNextB: MFTYODXH; BoxPrev: HCBALMVB; PortPrevFull: 1201/B; PortPrevShort: B; Fullname: TIID^Vertex Squeezer (EtherCAT)^SQZ Chassis 4 L0 (EK1101)^SQZ Chassis 4 L14 (EL2124); BoxAddr: 1202; Disabled: False
B925 = TerminalEL2124: EtherCAT Terminal EL2124 4-chn Digital Ouput; Rail: Left; BoxNextB: ARMEEXWF; BoxPrev: IADPCTYX; PortPrevFull: 1202/B; PortPrevShort: B; Fullname: TIID^Vertex Squeezer (EtherCAT)^SQZ Chassis 4 L0 (EK1101)^SQZ Chassis 4 L15 (EL2124); BoxAddr: 1203; Disabled: False
B926 = TerminalEL2124: EtherCAT Terminal EL2124 4-chn Digital Ouput; Rail: Left; BoxNextB: AFKWOLWJ; BoxPrev: MFTYODXH; PortPrevFull: 1203/B; PortPrevShort: B; Fullname: TIID^Vertex Squeezer (EtherCAT)^SQZ Chassis 4 L0 (EK1101)^SQZ Chassis 4 L16 (EL2124); BoxAddr: 1204; Disabled: False
B927 = TerminalEL9410: EtherCAT Terminal EL9410 Power; Rail: Left; BoxNextB: YRDXYOBE; BoxPrev: ARMEEXWF; PortPrevFull: 1204/B; PortPrevShort: B; Fullname: TIID^Vertex Squeezer (EtherCAT)^SQZ Chassis 4 L0 (EK1101)^SQZ Chassis 4 L17 (EL9410); BoxAddr: 1205; Disabled: False
B931 = TerminalEL3104: EtherCAT Terminal EL3104 4-chn Analog Input; Rail: Left; BoxNextB: FEGJMGJQ; BoxPrev: AFKWOLWJ; PortPrevFull: 1205/B; PortPrevShort: B; Fullname: TIID^Vertex Squeezer (EtherCAT)^SQZ Chassis 4 L0 (EK1101)^SQZ Chassis 4 L18 (EL3104); BoxAddr: 1206; Disabled: False
B932 = TerminalEL3104: EtherCAT Terminal EL3104 4-chn Analog Input; Rail: Left; BoxNextB: QSVIHKWD; BoxPrev: YRDXYOBE; PortPrevFull: 1206/B; PortPrevShort: B; Fullname: TIID^Vertex Squeezer (EtherCAT)^SQZ Chassis 4 L0 (EK1101)^SQZ Chassis 4 L19 (EL3104); BoxAddr: 1207; Disabled: False
B934 = CouplerEK1100: EtherCAT Coupler; Rail: Middle; BoxNextB: ELDBEGII; BoxNextC: CWDKXLUE; BoxPrev: BCNOLNHC; PortPrevFull: 1188/C; PortPrevShort: C 'X2 Out'; Fullname: TIID^Vertex Squeezer (EtherCAT)^SQZ Chassis 4 M0 (EK1100); BoxPorts: Junction; BoxAddr: 1214; Disabled: False
B935 = TerminalEL4132: EtherCAT Terminal EL4132 2-chn Analog Ouput; Rail: Left; BoxNextB: OPTEPMIG; BoxPrev: FEGJMGJQ; PortPrevFull: 1207/B; PortPrevShort: B; Fullname: TIID^Vertex Squeezer (EtherCAT)^SQZ Chassis 4 L0 (EK1101)^SQZ Chassis 4 L20 (EL4132); BoxAddr: 1208; Disabled: False
B936 = TerminalEL1124: EtherCAT Terminal EL1124 4-chn Digital Input; Rail: Left; BoxNextB: BNENHREX; BoxPrev: QSVIHKWD; PortPrevFull: 1208/B; PortPrevShort: B; Fullname: TIID^Vertex Squeezer (EtherCAT)^SQZ Chassis 4 L0 (EK1101)^SQZ Chassis 4 L21 (EL1124); BoxAddr: 1209; Disabled: False
B937 = TerminalEL2124: EtherCAT Terminal EL2124 4-chn Digital Ouput; Rail: Left; BoxNextB: IKRYUTNI; BoxPrev: OPTEPMIG; PortPrevFull: 1209/B; PortPrevShort: B; Fullname: TIID^Vertex Squeezer (EtherCAT)^SQZ Chassis 4 L0 (EK1101)^SQZ Chassis 4 L22 (EL2124); BoxAddr: 1210; Disabled: False
B938 = TerminalEL9190: EtherCAT Terminal EL9190 Supply; BoxType: TerminalPassive; Rail: Left; BoxNextB: SBVBAHED; BoxPrev: BNENHREX; PortPrevShort: B; Fullname: TIID^Vertex Squeezer (EtherCAT)^SQZ Chassis 4 L0 (EK1101)^SQZ Chassis 4 L23 (EL9190); Disabled: False
B939 = TerminalEL9410: EtherCAT Terminal EL9410 Power; Rail: Middle; BoxNextB: BFJWRYJE; BoxPrev: UHOWTQUC; PortPrevFull: 1219/B; PortPrevShort: B; Fullname: TIID^Vertex Squeezer (EtherCAT)^SQZ Chassis 4 M0 (EK1100)^SQZ Chassis 4 M6 (EL9410); BoxAddr: 1220; Disabled: False
B940 = TerminalEL3104: EtherCAT Terminal EL3104 4-chn Analog Input; Rail: Middle; BoxNextB: YSFCKDMX; BoxPrev: IINFKOSP; PortPrevFull: 1220/B; PortPrevShort: B; Fullname: TIID^Vertex Squeezer (EtherCAT)^SQZ Chassis 4 M0 (EK1100)^SQZ Chassis 4 M7 (EL3104); BoxAddr: 1221; Disabled: False
B941 = TerminalEL3104: EtherCAT Terminal EL3104 4-chn Analog Input; Rail: Middle; BoxNextB: RWEKLMHR; BoxPrev: BFJWRYJE; PortPrevFull: 1221/B; PortPrevShort: B; Fullname: TIID^Vertex Squeezer (EtherCAT)^SQZ Chassis 4 M0 (EK1100)^SQZ Chassis 4 M8 (EL3104); BoxAddr: 1222; Disabled: False
B942 = TerminalEL4132: EtherCAT Terminal EL4132 2-chn Analog Ouput; Rail: Middle; BoxNextB: WANNMKBA; BoxPrev: YSFCKDMX; PortPrevFull: 1222/B; PortPrevShort: B; Fullname: TIID^Vertex Squeezer (EtherCAT)^SQZ Chassis 4 M0 (EK1100)^SQZ Chassis 4 M9 (EL4132); BoxAddr: 1223; Disabled: False
B943 = TerminalEL1124: EtherCAT Terminal EL1124 4-chn Digital Input; Rail: Middle; BoxNextB: LQABHGNI; BoxPrev: RWEKLMHR; PortPrevFull: 1223/B; PortPrevShort: B; Fullname: TIID^Vertex Squeezer (EtherCAT)^SQZ Chassis 4 M0 (EK1100)^SQZ Chassis 4 M10 (EL1124); BoxAddr: 1224; Disabled: False
B944 = TerminalEL2124: EtherCAT Terminal EL2124 4-chn Digital Ouput; Rail: Middle; BoxNextB: SXFJKERQ; BoxPrev: WANNMKBA; PortPrevFull: 1224/B; PortPrevShort: B; Fullname: TIID^Vertex Squeezer (EtherCAT)^SQZ Chassis 4 M0 (EK1100)^SQZ Chassis 4 M11 (EL2124); BoxAddr: 1225; Disabled: False
B945 = TerminalEL9410: EtherCAT Terminal EL9410 Power; Rail: Middle; BoxNextB: XCBOHHOF; BoxPrev: LQABHGNI; PortPrevFull: 1225/B; PortPrevShort: B; Fullname: TIID^Vertex Squeezer (EtherCAT)^SQZ Chassis 4 M0 (EK1100)^SQZ Chassis 4 M12 (EL9410); BoxAddr: 1226; Disabled: False
B946 = TerminalEL7332: EtherCAT Terminal EL7332 2-channel DC motor output stage 24 V DC, 1 A; Rail: Right; BoxNextB: LYDHFSOS; BoxPrev: CWDKXLUE; PortPrevFull: 1240/B; PortPrevShort: B; Fullname: TIID^Vertex Squeezer (EtherCAT)^SQZ Chassis 4 R0 (EK1100)^SQZ Chassis 4 R1 (EL7332); BoxAddr: 1241; PDO Outputs: 0x1604,0x1605,0x1606,0x1607; PDO Inputs: 0x1A04,0x1A06; Disabled: False
B947 = TerminalEL1094: EtherCAT Terminal EL1094 4-channel digital input terminal 24 V DC, switching to negative potential; Rail: Right; BoxNextB: QWHNWNKG; BoxPrev: TPDTFVDF; PortPrevFull: 1241/B; PortPrevShort: B; Fullname: TIID^Vertex Squeezer (EtherCAT)^SQZ Chassis 4 R0 (EK1100)^SQZ Chassis 4 R2 (EL1094); BoxAddr: 1242; Disabled: False
B948 = TerminalEL1094: EtherCAT Terminal EL1094 4-channel digital input terminal 24 V DC, switching to negative potential; Rail: Right; BoxNextB: BNXOHIXO; BoxPrev: LYDHFSOS; PortPrevFull: 1242/B; PortPrevShort: B; Fullname: TIID^Vertex Squeezer (EtherCAT)^SQZ Chassis 4 R0 (EK1100)^SQZ Chassis 4 R3 (EL1094); BoxAddr: 1243; Disabled: False
B949 = TerminalEL2008: EtherCAT Terminal EL2008 8-channel digital output terminal 24 V DC, 0.5 A; Rail: Right; BoxNextB: REGWBYFR; BoxPrev: QWHNWNKG; PortPrevFull: 1243/B; PortPrevShort: B; Fullname: TIID^Vertex Squeezer (EtherCAT)^SQZ Chassis 4 R0 (EK1100)^SQZ Chassis 4 R4 (EL2008); BoxAddr: 1244; Disabled: False
B950 = TerminalEL3104: EtherCAT Terminal EL3104 4-chn Analog Input; Rail: Right; BoxNextB: JKGGPIQT; BoxPrev: BNXOHIXO; PortPrevFull: 1244/B; PortPrevShort: B; Fullname: TIID^Vertex Squeezer (EtherCAT)^SQZ Chassis 4 R0 (EK1100)^SQZ Chassis 4 R5 (EL3104); BoxAddr: 1245; Disabled: False
B951 = TerminalEL4134: EtherCAT Terminal EL4134 4-chn Analog Ouput; Rail: Right; BoxNextB: QKJDWDMX; BoxPrev: REGWBYFR; PortPrevFull: 1245/B; PortPrevShort: B; Fullname: TIID^Vertex Squeezer (EtherCAT)^SQZ Chassis 4 R0 (EK1100)^SQZ Chassis 4 R6 (EL4134); BoxAddr: 1246; Disabled: False
B952 = TerminalEL9410: EtherCAT Terminal EL9410 Power; Rail: Right; BoxNextB: FTNNSGCQ; BoxPrev: JKGGPIQT; PortPrevFull: 1246/B; PortPrevShort: B; Fullname: TIID^Vertex Squeezer (EtherCAT)^SQZ Chassis 4 R0 (EK1100)^SQZ Chassis 4 R7 (EL9410); BoxAddr: 1247; Disabled: False
B953 = TerminalEL3104: EtherCAT Terminal EL3104 4-chn Analog Input; Rail: Right; BoxNextB: JRLCSSOT; BoxPrev: QKJDWDMX; PortPrevFull: 1247/B; PortPrevShort: B; Fullname: TIID^Vertex Squeezer (EtherCAT)^SQZ Chassis 4 R0 (EK1100)^SQZ Chassis 4 R8 (EL3104); BoxAddr: 1248; Disabled: False
B954 = TerminalEL1124: EtherCAT Terminal EL1124 4-chn Digital Input; Rail: Right; BoxNextB: PDIXAHWP; BoxPrev: FTNNSGCQ; PortPrevFull: 1248/B; PortPrevShort: B; Fullname: TIID^Vertex Squeezer (EtherCAT)^SQZ Chassis 4 R0 (EK1100)^SQZ Chassis 4 R9 (EL1124); BoxAddr: 1249; Disabled: False
B955 = TerminalEL2124: EtherCAT Terminal EL2124 4-chn Digital Ouput; Rail: Right; BoxNextB: MTEEATIO; BoxPrev: JRLCSSOT; PortPrevFull: 1249/B; PortPrevShort: B; Fullname: TIID^Vertex Squeezer (EtherCAT)^SQZ Chassis 4 R0 (EK1100)^SQZ Chassis 4 R10 (EL2124); BoxAddr: 1250; Disabled: False
B956 = TerminalEL9190: EtherCAT Terminal EL9190 Supply; BoxType: TerminalPassive; Rail: Right; BoxNextB: BWTDWNLT; BoxPrev: PDIXAHWP; PortPrevShort: B; Fullname: TIID^Vertex Squeezer (EtherCAT)^SQZ Chassis 4 R0 (EK1100)^SQZ Chassis 4 R11 (EL9190); Disabled: False
B957 = TerminalEL3104: EtherCAT Terminal EL3104 4-chn Analog Input; Rail: Right; BoxNextB: RYFBUDYX; BoxPrev: MTEEATIO; PortPrevFull: 1250/B; PortPrevShort: B; Fullname: TIID^Vertex Squeezer (EtherCAT)^SQZ Chassis 4 R0 (EK1100)^SQZ Chassis 4 R12 (EL3104); BoxAddr: 1251; Disabled: False
B958 = CouplerEK1100: EtherCAT Coupler; Rail: Right; BoxNextB: TPDTFVDF; BoxNextC: JQVLJOFM; BoxPrev: CKSSHHCU; PortPrevFull: 1214/C; PortPrevShort: C 'X2 Out'; Fullname: TIID^Vertex Squeezer (EtherCAT)^SQZ Chassis 4 R0 (EK1100); BoxPorts: Junction; BoxAddr: 1240; Disabled: False
B959 = TerminalEL3104: EtherCAT Terminal EL3104 4-chn Analog Input; Rail: Right; BoxNextB: YIKBAUCF; BoxPrev: BWTDWNLT; PortPrevFull: 1251/B; PortPrevShort: B; Fullname: TIID^Vertex Squeezer (EtherCAT)^SQZ Chassis 4 R0 (EK1100)^SQZ Chassis 4 R13 (EL3104); BoxAddr: 1252; Disabled: False
B960 = TerminalEL9011: EtherCAT Terminal EL9011 End; BoxType: TerminalPassive; Rail: Right; BoxPrev: RYFBUDYX; PortPrevShort: B; Fullname: TIID^Vertex Squeezer (EtherCAT)^SQZ Chassis 4 R0 (EK1100)^SQZ Chassis 4 R14 (EL9011); Disabled: False
B973 = TerminalEL3104: EtherCAT Terminal EL3104 4-chn Analog Input; Rail: Middle; BoxNextB: SDQOLRRP; BoxPrev: CKSSHHCU; PortPrevFull: 1214/B; PortPrevShort: B; Fullname: TIID^Vertex Squeezer (EtherCAT)^SQZ Chassis 4 M0 (EK1100)^SQZ Chassis 4 M1 (EL3104); BoxAddr: 1215; Disabled: False
B974 = TerminalEL3104: EtherCAT Terminal EL3104 4-chn Analog Input; Rail: Middle; BoxNextB: QIYXPMNR; BoxPrev: ELDBEGII; PortPrevFull: 1215/B; PortPrevShort: B; Fullname: TIID^Vertex Squeezer (EtherCAT)^SQZ Chassis 4 M0 (EK1100)^SQZ Chassis 4 M2 (EL3104); BoxAddr: 1216; Disabled: False
B975 = TerminalEL4132: EtherCAT Terminal EL4132 2-chn Analog Ouput; Rail: Middle; BoxNextB: WGAIHOVS; BoxPrev: SDQOLRRP; PortPrevFull: 1216/B; PortPrevShort: B; Fullname: TIID^Vertex Squeezer (EtherCAT)^SQZ Chassis 4 M0 (EK1100)^SQZ Chassis 4 M3 (EL4132); BoxAddr: 1217; Disabled: False
B976 = TerminalEL1124: EtherCAT Terminal EL1124 4-chn Digital Input; Rail: Middle; BoxNextB: UHOWTQUC; BoxPrev: QIYXPMNR; PortPrevFull: 1217/B; PortPrevShort: B; Fullname: TIID^Vertex Squeezer (EtherCAT)^SQZ Chassis 4 M0 (EK1100)^SQZ Chassis 4 M4 (EL1124); BoxAddr: 1218; Disabled: False
B977 = TerminalEL2124: EtherCAT Terminal EL2124 4-chn Digital Ouput; Rail: Middle; BoxNextB: IINFKOSP; BoxPrev: WGAIHOVS; PortPrevFull: 1218/B; PortPrevShort: B; Fullname: TIID^Vertex Squeezer (EtherCAT)^SQZ Chassis 4 M0 (EK1100)^SQZ Chassis 4 M5 (EL2124); BoxAddr: 1219; Disabled: False
V744 = CommonMode_CommonModeInStructB: CommonModeInStruct; BoxType: Variable; Instance: H1SqzCorner Instance; PLC: H1SqzCorner; Task: SqzCStd
V745 = CommonMode_CommonModeOutStructC: CommonModeOutStruct; BoxType: Variable; Instance: H1SqzCorner Instance; PLC: H1SqzCorner; Task: SqzCStd
V747 = LowNoiseVco_LowNoiseVcoOutStruct: LowNoiseVcoOutStruct; BoxType: Variable; Instance: H1SqzCorner Instance; PLC: H1SqzCorner; Task: SqzCStd
V748 V749 = BeamDiverter_BeamDiverterOutStruct: BeamDiverterOutStruct; BoxType: Variable; Instance: H1AuxCorner Instance; PLC: H1AuxCorner; Task: AuxCStd
V774 V776 = Vcxo_VcxoInStruct: VcxoInStruct; BoxType: Variable; Instance: H1SqzCorner Instance; PLC: H1SqzCorner; Task: SqzCStd
V775 V777 = Vcxo_VcxoOutStruct: VcxoOutStruct; BoxType: Variable; Instance: H1SqzCorner Instance; PLC: H1SqzCorner; Task: SqzCStd
V778 V779 = BeamDiverter_BeamDiverterInStruct: BeamDiverterInStruct; BoxType: Variable; Instance: H1AuxCorner Instance; PLC: H1AuxCorner; Task: AuxCStd
V780-V783 = ShutterControl_ShutterControlInStruct: ShutterControlInStruct; BoxType: Variable; Instance: H1AuxCorner Instance; PLC: H1AuxCorner; Task: AuxCStd
V784-V787 = ShutterControl_ShutterControlOutStruct: ShutterControlOutStruct; BoxType: Variable; Instance: H1AuxCorner Instance; PLC: H1AuxCorner; Task: AuxCStd
V796 = LowNoiseVco_LowNoiseVcoInStructB: LowNoiseVcoInStruct; BoxType: Variable; Instance: H1SqzCorner Instance; PLC: H1SqzCorner; Task: SqzCStd
V797 = LowNoiseVco_PllIntegrationIn: PllIntegrationInStruct; BoxType: Variable; Instance: H1SqzCorner Instance; PLC: H1SqzCorner; Task: SqzCStd
V798 = LowNoiseVco_PllIntegrationOut: PllIntegrationOutStruct; BoxType: Variable; Instance: H1SqzCorner Instance; PLC: H1SqzCorner; Task: SqzCStd
V799 V800 = DCPower_QuadDCPowerInStruct: QuadDCPowerInStruct; BoxType: Variable; Instance: H1SqzCorner Instance; PLC: H1SqzCorner; Task: SqzCStd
